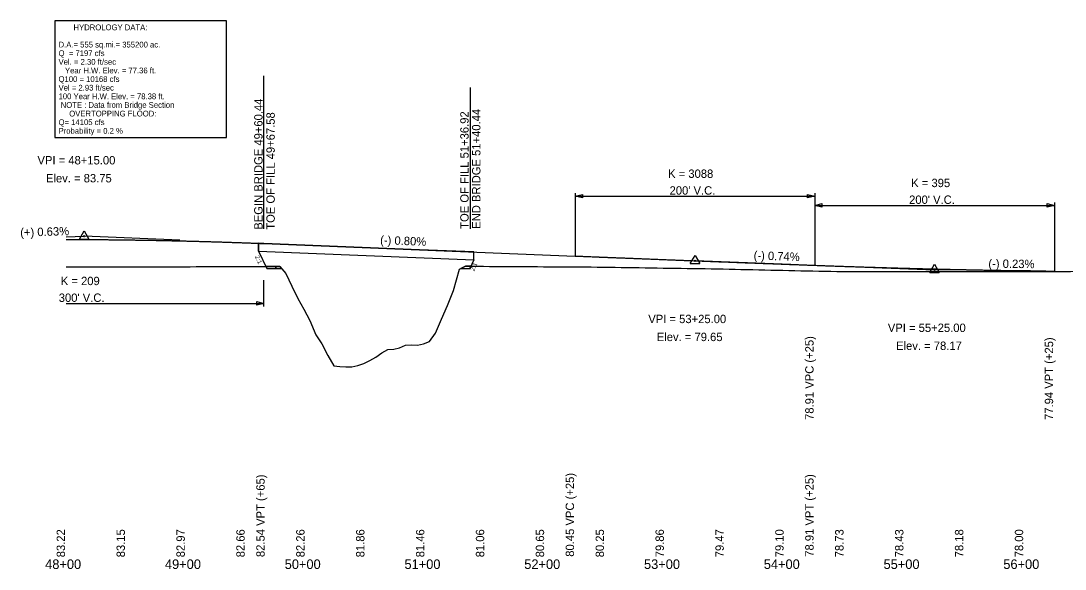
# Model space of a CAD drawing. Extents: x -3336 to 3318, y -3606 to 6276.
# Drawn here: x -38 to 834, y 641 to 1099 of the extents above; entities that cross this region are included whole.
import ezdxf

# ---------------------------------------------------------------- set-up
doc = ezdxf.new("R2010")
doc.units = 0
for name, color, linetype in [('RD_DDB_GradeTX', 7, 'Continuous'), ('RD_DDB_Profile_EX', 7, 'Continuous'), ('RD_DDB_Profile_Lbl', 7, 'Continuous'), ('RD_DDB_Profile_PR', 7, 'Continuous'), ('RD_DDB_StaTX', 7, 'Continuous'), ('RD_DDB_StripGrade', 7, 'Continuous'), ('RD_DDB_VCLbl', 7, 'Continuous'), ('RD_HC_Data', 7, 'Continuous'), ('RD_TX_Drainage', 7, 'Continuous'), ('RD_TX_Profile', 7, 'Continuous'), ('RD_XS_TieSlope', 7, 'Continuous')]:
    doc.layers.add(name, color=color, linetype=linetype)

msp = doc.modelspace()

# ---------------------------------------------------------------- linework, layer by layer
at = {"layer": 'RD_DDB_GradeTX'}
for p, q in [((0, 918.28), (15, 918.75)), ((94.94, 915.54), (15, 918.75)), ((445.06, 901.46), (525, 898.25)), ((604.95, 895.3), (525, 898.25)), ((645.05, 893.81), (725, 890.86)), ((804.99, 889.93), (725, 890.86))]:
    msp.add_line(p, q, dxfattribs=at)
at = {"layer": 'RD_DDB_Profile_EX'}
for points in [[(0, 893.33), (3.38, 893.33), (8.38, 893.32), (13.38, 893.32), (18.38, 893.31), (23.38, 893.31), (28.38, 893.31), (33.38, 893.31), (38.38, 893.3), (43.38, 893.3), (48.38, 893.29), (53.38, 893.29), (58.38, 893.29), (63.38, 893.29), (68.38, 893.28), (73.38, 893.28), (78.38, 893.28), (83.38, 893.32), (88.38, 893.34), (93.38, 893.35), (98.38, 893.37), (103.38, 893.38), (108.38, 893.42), (113.38, 893.44), (118.38, 893.45), (123.38, 893.47), (128.38, 893.48), (133.38, 893.52), (138.38, 893.54), (143.38, 893.55), (148.38, 893.57), (153.38, 893.58), (158.38, 893.61), (163.38, 893.63), (168.38, 893.64), (173.38, 893.66), (178.38, 893.67), (183.38, 887.6), (188.38, 877.22), (193.38, 866.83), (198.38, 857.78), (203.38, 848.42), (208.38, 836.44), (213.38, 828.96), (218.38, 819.11), (223.38, 810.74), (228.38, 810), (233.38, 809.76), (238.38, 809.76), (243.38, 810.86), (248.38, 812.66), (253.38, 815.13), (258.38, 817.97), (263.38, 821.43), (268.38, 824.23), (273.38, 824.42), (278.38, 825.62), (283.38, 827.82), (288.38, 828.22), (293.38, 827.98), (298.38, 829.06), (303.38, 830.78), (308.38, 837.88), (313.38, 849.45), (318.38, 861.01), (323.38, 873.51), (328.38, 891.43), (333.38, 893.78), (338.38, 893.75), (343.38, 893.72), (348.38, 893.69), (353.38, 893.66), (358.38, 893.63), (363.38, 893.6), (368.38, 893.57), (373.38, 893.54), (378.38, 893.51), (383.38, 893.48), (388.38, 893.45), (393.38, 893.42), (398.38, 893.39), (403.38, 893.36), (408.38, 893.33), (413.38, 893.3), (418.38, 893.27), (423.38, 893.24), (428.38, 893.21), (433.38, 893.18), (438.38, 893.15), (443.38, 893.11), (448.38, 893.03), (453.38, 892.96), (458.38, 892.88), (463.38, 892.81), (468.38, 892.73), (473.38, 892.65), (478.38, 892.57), (483.38, 892.5), (488.38, 892.42), (493.38, 892.34), (498.38, 892.26)], [(498.38, 892.26), (503.38, 892.19), (508.38, 892.11), (513.38, 892.04), (518.38, 891.96), (523.38, 891.88), (528.38, 891.81), (533.38, 891.73), (538.38, 891.66), (543.38, 891.58), (548.38, 891.48), (553.38, 891.36), (558.38, 891.25), (563.38, 891.14), (568.38, 891.03), (573.38, 890.92), (578.38, 890.81), (583.38, 890.7), (588.38, 890.59), (593.38, 890.48), (598.38, 890.38), (603.38, 890.27), (608.38, 890.15), (613.38, 890.04), (618.38, 889.94), (623.38, 889.83), (628.38, 889.72), (633.38, 889.61), (638.38, 889.5), (643.38, 889.4), (648.38, 889.31), (653.38, 889.31), (658.38, 889.31), (663.38, 889.3), (668.38, 889.3), (673.38, 889.28), (678.38, 889.28), (683.38, 889.28), (688.38, 889.28), (693.38, 889.28), (698.38, 889.27), (703.38, 889.27), (708.38, 889.26), (713.38, 889.26), (718.38, 889.26), (723.38, 889.26), (728.38, 889.26), (733.38, 889.26), (738.38, 889.26), (743.38, 889.26), (748.38, 889.26), (753.38, 889.27), (758.38, 889.27), (763.38, 889.28), (768.38, 889.29), (773.38, 889.3), (778.38, 889.3), (783.38, 889.31), (788.38, 889.32), (793.38, 889.32), (798.38, 889.33), (803.38, 889.34), (808.38, 889.35), (813.38, 889.35), (818.38, 889.36), (823.38, 889.37), (828.38, 889.37), (833.38, 889.38), (838.38, 889.39)]]:
    msp.add_lwpolyline(points, dxfattribs=at)
at = {"layer": 'RD_DDB_Profile_PR'}
for p, q in [((160.44, 906.25), (160.44, 912.9)), ((165, 912.72), (425, 902.27)), ((160.44, 906.25), (340.44, 899.01)), ((340.44, 899.01), (340.44, 905.67)), ((825, 889.69), (850, 889.4))]:
    msp.add_line(p, q, dxfattribs=at)
msp.add_lwpolyline([(340.44, 899.01), (340.44, 905.67), (295, 907.5), (165, 912.72), (160.44, 912.9), (160.44, 906.25)], close=True, dxfattribs=at)
for points in [[(0, 916.1), (3.3, 916.1), (6.6, 916.09), (9.9, 916.08), (13.2, 916.07), (16.5, 916.06), (19.8, 916.04), (23.1, 916.02), (26.4, 916), (29.7, 915.97), (33, 915.95), (36.3, 915.92), (39.6, 915.88), (42.9, 915.85), (46.2, 915.81), (49.5, 915.77), (52.8, 915.73), (56.1, 915.68), (59.4, 915.63), (62.7, 915.58), (66, 915.53), (69.3, 915.47), (72.6, 915.41), (75.9, 915.35), (79.2, 915.29), (82.5, 915.22), (85.8, 915.15), (89.1, 915.08), (92.4, 915.01), (95.7, 914.93), (99, 914.85), (102.3, 914.77), (105.6, 914.69), (108.9, 914.6), (112.2, 914.51), (115.5, 914.42), (118.8, 914.32), (122.1, 914.23), (125.4, 914.13), (128.7, 914.02), (132, 913.92), (135.3, 913.81), (138.6, 913.7), (141.9, 913.59), (145.2, 913.47), (148.5, 913.35), (151.8, 913.23), (155.1, 913.11), (158.4, 912.98), (161.7, 912.85), (165, 912.72)], [(425, 902.27), (429, 902.11), (433, 901.95), (437, 901.79), (441, 901.63), (445, 901.47), (449, 901.31), (453, 901.15), (457, 900.99), (461, 900.83), (465, 900.67), (469, 900.52), (473, 900.36), (477, 900.2), (481, 900.04), (485, 899.89), (489, 899.73), (493, 899.57), (497, 899.42), (501, 899.26), (505, 899.11), (509, 898.95), (513, 898.8), (517, 898.64), (521, 898.49), (525, 898.33), (529, 898.18), (533, 898.02), (537, 897.87), (541, 897.72), (545, 897.56), (549, 897.41), (553, 897.26), (557, 897.1), (561, 896.95), (565, 896.8), (569, 896.65), (573, 896.5), (577, 896.35), (581, 896.2), (585, 896.05), (589, 895.9), (593, 895.75), (597, 895.6), (601, 895.45), (605, 895.3), (609, 895.15), (613, 895), (617, 894.85), (621, 894.7), (625, 894.55)], [(625, 894.55), (629, 894.41), (633, 894.26), (637, 894.12), (641, 893.98), (645, 893.84), (649, 893.7), (653, 893.57), (657, 893.44), (661, 893.31), (665, 893.18), (669, 893.05), (673, 892.93), (677, 892.8), (681, 892.68), (685, 892.56), (689, 892.45), (693, 892.33), (697, 892.22), (701, 892.11), (705, 892), (709, 891.9), (713, 891.79), (717, 891.69), (721, 891.59), (725, 891.49), (729, 891.39), (733, 891.3), (737, 891.21), (741, 891.12), (745, 891.03), (749, 890.94), (753, 890.86), (757, 890.78), (761, 890.7), (765, 890.62), (769, 890.54), (773, 890.47), (777, 890.4), (781, 890.33), (785, 890.26), (789, 890.19), (793, 890.13), (797, 890.07), (801, 890.01), (805, 889.95), (809, 889.89), (813, 889.84), (817, 889.79), (821, 889.74), (825, 889.69)]]:
    msp.add_spline(points, degree=3, dxfattribs=at)
at = {"layer": 'RD_DDB_StripGrade'}
for p, q in [((164.87, 925), (164.87, 1052.65)), ((337.45, 925), (337.45, 1043.06)), ((166.76, 893.64), (167.58, 892)), ((167.58, 892), (175, 892)), ((175, 892), (175, 893.66)), ((175, 893.66), (175, 892)), ((175, 892), (179.76, 892)), ((333.38, 893.78), (329.58, 892)), ((329.58, 892), (336.92, 892)), ((337.81, 893.76), (333.38, 893.78)), ((336.92, 892), (337.81, 893.76))]:
    msp.add_line(p, q, dxfattribs=at)
for points in [[(175, 893.66), (173.38, 893.66), (168.38, 893.64), (166.76, 893.64)], [(179.76, 892), (178.38, 893.67), (175, 893.66)]]:
    msp.add_lwpolyline(points, dxfattribs=at)
at = {"layer": 'RD_DDB_VCLbl'}
for p, q in [((425, 954.77), (425, 902.27)), ((425, 952.27), (625, 952.27)), ((625, 954.77), (625, 894.55)), ((625, 947.05), (625, 894.55)), ((625, 944.55), (825, 944.55)), ((825, 947.05), (825, 889.69)), ((165, 860.22), (165, 882.21)), ((0, 862.72), (165, 862.72))]:
    msp.add_line(p, q, dxfattribs=at)
at = {"layer": 'RD_HC_Data'}
for p, q in [((11.03, 916.46), (15, 923.34)), ((11.03, 916.46), (18.97, 916.46)), ((15, 923.34), (18.97, 916.46)), ((521.03, 895.96), (525, 902.84)), ((525, 902.84), (528.97, 895.96)), ((521.03, 895.96), (528.97, 895.96)), ((721.03, 888.57), (725, 895.45)), ((725, 895.45), (728.97, 888.57)), ((721.03, 888.57), (728.97, 888.57))]:
    msp.add_line(p, q, dxfattribs=at)
for centre in [(15, 918.75), (525, 898.25), (725, 890.86)]:
    msp.add_circle(centre, 0.529, dxfattribs=at)
at = {"layer": 'RD_TX_Drainage'}
for points in [[(431, 950.77), (425, 952.27), (431, 953.77)], [(619, 953.77), (625, 952.27), (619, 950.77)], [(631, 943.05), (625, 944.55), (631, 946.05)], [(819, 946.05), (825, 944.55), (819, 943.05)], [(159, 864.22), (165, 862.72), (159, 861.22)]]:
    msp.add_lwpolyline(points, close=True, dxfattribs=at)
at = {"layer": 'RD_TX_Profile'}
msp.add_lwpolyline([(-9.41, 1001.34), (133.76, 1001.34), (133.76, 1098.59), (-9.41, 1098.59)], close=True, dxfattribs=at)
at = {"layer": 'RD_XS_TieSlope'}
for p, q in [((160.44, 906.25), (167.58, 892)), ((340.44, 899.01), (336.92, 892))]:
    msp.add_line(p, q, dxfattribs=at)

# ---------------------------------------------------------------- texts
at = {"layer": 'RD_DDB_GradeTX'}
for s, rotation, p in [('(+) 0.63%', 1.80292, (-38.33, 918.41)), ('(-) 0.80%', 357.69817, (261.98, 912.27)), ('(-) 0.74%', 357.88343, (573.83, 899.47)), ('(-) 0.23%', 359.33154, (769.89, 892.54))]:
    msp.add_text(s, height=7, rotation=rotation, dxfattribs=at).set_placement(p)
at = {"layer": 'RD_DDB_Profile_Lbl'}
for s, p in [('VPI = 48+15.00', (-24.03, 978.75)), ('Elev. = 83.75', (-16.92, 963.75)), ('VPI = 53+25.00', (485.97, 846.25)), ('VPI = 55+25.00', (685.97, 838.86)), ('Elev. = 79.65', (493.08, 831.25)), ('Elev. = 78.17', (692.88, 823.86))]:
    msp.add_text(s, height=7, dxfattribs=at).set_placement(p)
at = {"layer": 'RD_DDB_StaTX'}
for s, p in [('48+00', (-17.59, 641)), ('49+00', (82.41, 641)), ('50+00', (182.41, 641)), ('51+00', (282.41, 641)), ('52+00', (382.41, 641)), ('53+00', (482.41, 641)), ('54+00', (582.41, 641)), ('55+00', (682.41, 641)), ('56+00', (782.41, 641))]:
    msp.add_text(s, height=8, dxfattribs=at).set_placement(p)
at = {"layer": 'RD_DDB_StripGrade'}
for s, p in [('BEGIN BRIDGE 49+60.44', (163.93, 924.22)), ('TOE OF FILL 49+67.58', (174.1, 924.22)), ('TOE OF FILL 51+36.92', (335.98, 925)), ('END BRIDGE 51+40.44', (345.82, 925)), ('78.91 VPC (+25)', (624, 765.42)), ('77.94 VPT (+25)', (824, 765.42)), ('82.54 VPT (+65)', (165.68, 650.92)), ('80.45 VPC (+25)', (424, 651.21)), ('78.91 VPT (+25)', (624, 651.21)), ('83.22', (-1, 650.75)), ('83.15', (49, 650.75)), ('82.97', (99, 650.75)), ('82.66', (149, 650.75)), ('82.26', (199, 650.75)), ('81.86', (249, 650.75)), ('81.46', (299, 650.75)), ('81.06', (349, 650.75)), ('80.65', (399, 650.75)), ('80.25', (449, 650.75)), ('79.86', (499, 650.75)), ('79.47', (549, 650.75)), ('79.10', (599, 650.75)), ('78.73', (649, 650.75)), ('78.43', (699, 650.75)), ('78.18', (749, 650.75)), ('78.00', (799, 650.75))]:
    msp.add_text(s, height=7, rotation=90, dxfattribs=at).set_placement(p)
at = {"layer": 'RD_DDB_VCLbl'}
for s, p in [('K = 3088', (502.5, 967.52)), ("200' V.C.", (503.75, 953.52)), ('K = 395', (705.48, 959.8)), ("200' V.C.", (703.75, 945.8)), ('K = 209', (-4.56, 877.97)), ("300' V.C.", (-6.25, 863.97))]:
    msp.add_text(s, height=7, dxfattribs=at).set_placement(p)
for rotation, p in [(293.62274, (157.48, 901.79)), (66.37726, (340.52, 889.34))]:
    msp.add_text('2:1', height=3.72, rotation=rotation, dxfattribs=at).set_placement(p)
at = {"layer": 'RD_TX_Profile'}
for s, p in [('       HYDROLOGY DATA:', (-6.41, 1090.79)), ('D.A.= 555 sq.mi.= 355200 ac.', (-6.41, 1076.39)), ('Q  = 7197 cfs', (-6.41, 1069.19)), ('Vel. = 2.30 ft/sec', (-6.41, 1061.99)), ('   Year H.W. Elev. = 77.36 ft.', (-6.41, 1054.79)), ('Q100 = 10168 cfs', (-6.41, 1047.59)), ('Vel = 2.93 ft/sec', (-6.41, 1040.39)), ('100 Year H.W. Elev. = 78.38 ft.', (-6.41, 1033.19)), (' NOTE : Data from Bridge Section', (-6.41, 1025.99)), ('     OVERTOPPING FLOOD:', (-6.41, 1018.79)), ('Q= 14105 cfs', (-6.41, 1011.59)), ('Probability = 0.2 %', (-6.41, 1004.39))]:
    msp.add_text(s, height=4.8, dxfattribs=at).set_placement(p)

doc.saveas('drawing.dxf')
